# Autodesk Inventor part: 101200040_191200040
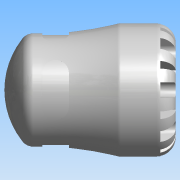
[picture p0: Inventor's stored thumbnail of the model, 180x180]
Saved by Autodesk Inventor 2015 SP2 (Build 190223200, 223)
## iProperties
Created: 2016-12
Part Number: 101200040_191200040
Material: PVC-Piping
Description: PLASSON END PLUG 40 SERIES 1
Document SubType Name: Modeling
Designer: KIM
Mass: 57.8335 g
Surface Area: 121.129 cm^2
Volume: 41.3096 cm^3
Density: 1.4 g/cm^3
Appearance: Smooth - White
Author: KIM
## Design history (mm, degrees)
derived "1012.ipt"
feature "Solid1::1012.ipt"
tag "TaggingFeature1"
body "Solid1"
other parameters: "d1" = 29.82, "d6" = 71, "d7" = 78.1, "d8" = 59.5, "d13" = 8, "d14" = 8, "d15" = 0, "d17" = 360 deg, "d19" = 8 deg, "d20" = 0.8, "d21" = 0.8, "d22" = 8 deg, "d24" = 0, "d26" = 360 deg, "d32" = 7, "d33" = 7, "d34" = 8.8, "d35" = 14, "d36" = 15.68, "d37" = 0, "d42" = 360 deg, "d45" = 11.9, "d46" = 0.8, "d48" = 0, "d49" = 0.7, "l_" = 71, "d9" = 10
